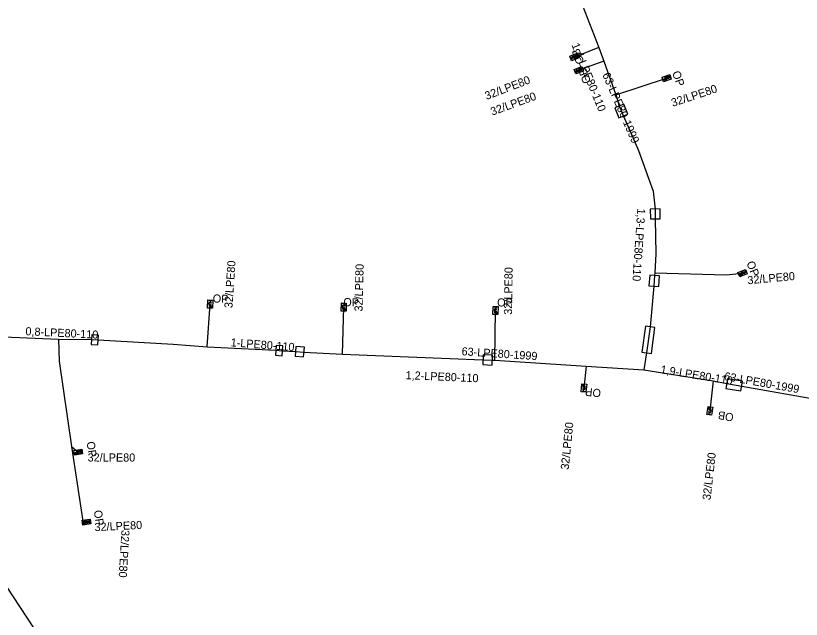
# Model space of a CAD drawing. Extents: x -762509 to -761250, y -1153000 to -1152256.
# Drawn here: x -761534.3 to -761437.4, y -1152558.6 to -1152484.2 of the extents above; entities that cross this region are included whole.
import ezdxf

# ---------------------------------------------------------------- set-up
doc = ezdxf.new("R2010")
doc.units = 0
for name, color, linetype in [('Vrstva 21', 7, 'Continuous'), ('Vrstva 29', 7, 'Continuous'), ('Vrstva 31', 7, 'Continuous'), ('Vrstva 32', 7, 'Continuous')]:
    doc.layers.add(name, color=color, linetype=linetype)

msp = doc.modelspace()

# ---------------------------------------------------------------- linework, layer by layer
at = {"layer": 'Vrstva 21'}
for points in [[(-761466.1, -1152478.45), (-761462.35, -1152488.13), (-761461.73, -1152489.79), (-761460.26, -1152493.95), (-761459.84, -1152495.33), (-761459.33, -1152496.58), (-761457.49, -1152500.82), (-761455.66, -1152505.82), (-761455.42, -1152508.04), (-761455.4, -1152509.24), (-761455.33, -1152513.56), (-761455.47, -1152515.91), (-761455.49, -1152516.25), (-761455.58, -1152517.56), (-761456.03, -1152522.58), (-761456.47, -1152525.78), (-761456.83, -1152527.87)], [(-761556.37, -1152527.31), (-761556.21, -1152527.12), (-761552.23, -1152522.56), (-761550.25, -1152522.69), (-761542.52, -1152523.31), (-761535.75, -1152523.8), (-761529, -1152524.1), (-761524.95, -1152524.15), (-761524.13, -1152524.19), (-761514.88, -1152524.71), (-761510.67, -1152525.03), (-761502.21, -1152525.46), (-761501.38, -1152525.53), (-761499.78, -1152525.61), (-761498.74, -1152525.69), (-761493.99, -1152525.96), (-761476.66, -1152526.63), (-761475.5, -1152526.68), (-761475.2, -1152526.7), (-761463.93, -1152527.44), (-761456.83, -1152527.87)], [(-761555.86, -1152527.89), (-761549.23, -1152535.25), (-761546.63, -1152538.48), (-761545.44, -1152539.91), (-761544.54, -1152541.17), (-761537.84, -1152551.04), (-761536.98, -1152552.22), (-761535.54, -1152554.43), (-761529.45, -1152563.76), (-761525.2, -1152570.86), (-761520.77, -1152578.65), (-761517.06, -1152586.65), (-761515.83, -1152589.42), (-761514.08, -1152593.75), (-761509.53, -1152605.92), (-761503.36, -1152620.97), (-761502.33, -1152623.3), (-761499.83, -1152629.35)], [(-761456.83, -1152527.87), (-761448.25, -1152529.25), (-761446.58, -1152529.57), (-761444.73, -1152529.87), (-761425.09, -1152533.35), (-761412.86, -1152535.83), (-761404.73, -1152537.14), (-761396.67, -1152538.6), (-761395, -1152538.89), (-761392.98, -1152539.26), (-761384.89, -1152540.72), (-761378.87, -1152541.76), (-761369.46, -1152544.68), (-761366.06, -1152546), (-761363.94, -1152546.96), (-761363.78, -1152547.02), (-761358.42, -1152549.62), (-761356.97, -1152550.5), (-761355.51, -1152551.26), (-761353.56, -1152552.55), (-761349.19, -1152555.34), (-761336.19, -1152563.79)]]:
    msp.add_lwpolyline(points, dxfattribs=at)
at = {"layer": 'Vrstva 29'}
for points in [[(-761460.4, -1152495.56), (-761459.89, -1152496.81), (-761458.77, -1152496.35), (-761459.28, -1152495.1)], [(-761456.02, -1152508.05), (-761456, -1152509.25), (-761454.8, -1152509.23), (-761454.82, -1152508.03)], [(-761456.09, -1152516.21), (-761456.18, -1152517.52), (-761454.98, -1152517.6), (-761454.89, -1152516.29)], [(-761455.88, -1152525.86), (-761455.44, -1152522.66), (-761456.62, -1152522.5), (-761457.06, -1152525.7)], [(-761524.98, -1152524.75), (-761524.16, -1152524.79), (-761524.1, -1152523.59), (-761524.92, -1152523.55)], [(-761502.26, -1152526.06), (-761501.43, -1152526.13), (-761501.33, -1152524.93), (-761502.16, -1152524.86)], [(-761499.83, -1152526.21), (-761498.79, -1152526.29), (-761498.69, -1152525.09), (-761499.73, -1152525.01)], [(-761476.69, -1152527.23), (-761475.53, -1152527.28), (-761475.47, -1152526.08), (-761476.63, -1152526.03)], [(-761446.68, -1152530.16), (-761444.83, -1152530.46), (-761444.63, -1152529.28), (-761446.48, -1152528.98)]]:
    msp.add_lwpolyline(points, close=True, dxfattribs=at)
at = {"layer": 'Vrstva 31'}
for points in [[(-761462.35, -1152488.13), (-761465.38, -1152489.29)], [(-761461.73, -1152489.79), (-761464.82, -1152490.92)], [(-761460.26, -1152493.95), (-761454, -1152491.89)], [(-761455.47, -1152515.91), (-761446.66, -1152516.14), (-761444.63, -1152515.95)], [(-761510.67, -1152525.03), (-761510.31, -1152519.76)], [(-761493.99, -1152525.96), (-761493.84, -1152520.13)], [(-761475.2, -1152526.7), (-761475.11, -1152520.56)], [(-761529, -1152524.1), (-761528.95, -1152526.81), (-761527.42, -1152537.35)], [(-761463.93, -1152527.44), (-761464.2, -1152530.12)], [(-761448.25, -1152529.25), (-761448.68, -1152532.94)], [(-761527.42, -1152537.35), (-761526.01, -1152546.55), (-761525.58, -1152546.66)], [(-761527.42, -1152537.35), (-761526.59, -1152538.03)]]:
    msp.add_lwpolyline(points, dxfattribs=at)
at = {"layer": 'Vrstva 32'}
for p, q in [((-761465.816, -1152489.269), (-761465.691, -1152489.596)), ((-761465.757, -1152489.423), (-761465.569, -1152489.352)), ((-761465.503, -1152489.524), (-761465.628, -1152489.198)), ((-761465.131, -1152489.382), (-761465.256, -1152489.055)), ((-761465.256, -1152490.893), (-761465.136, -1152491.222)), ((-761465.199, -1152491.048), (-761465.01, -1152490.979)), ((-761464.947, -1152491.153), (-761465.067, -1152490.824)), ((-761464.572, -1152491.015), (-761464.692, -1152490.687)), ((-761454.246, -1152491.791), (-761454.131, -1152492.122)), ((-761453.87, -1152491.659), (-761453.754, -1152491.99)), ((-761453.619, -1152491.767), (-761453.809, -1152491.834)), ((-761453.564, -1152491.923), (-761453.68, -1152491.593)), ((-761444.193, -1152515.962), (-761444.325, -1152515.637)), ((-761444.881, -1152515.862), (-761444.75, -1152516.187)), ((-761444.511, -1152515.713), (-761444.38, -1152516.037)), ((-761444.255, -1152515.809), (-761444.442, -1152515.884)), ((-761510.125, -1152519.364), (-761510.475, -1152519.356)), ((-761510.29, -1152519.36), (-761510.295, -1152519.561)), ((-761510.49, -1152519.956), (-761510.14, -1152519.964)), ((-761510.48, -1152519.557), (-761510.13, -1152519.565)), ((-761494.02, -1152520.325), (-761493.671, -1152520.335)), ((-761494.009, -1152519.926), (-761493.659, -1152519.936)), ((-761493.653, -1152519.735), (-761494.003, -1152519.725)), ((-761493.818, -1152519.73), (-761493.824, -1152519.931)), ((-761475.28, -1152520.357), (-761474.93, -1152520.366)), ((-761474.926, -1152520.165), (-761475.275, -1152520.156)), ((-761475.091, -1152520.161), (-761475.095, -1152520.362)), ((-761475.29, -1152520.756), (-761474.94, -1152520.764)), ((-761464.006, -1152529.938), (-761464.354, -1152529.903)), ((-761464.415, -1152530.5), (-761464.066, -1152530.535)), ((-761464.046, -1152530.335), (-761464.394, -1152530.3)), ((-761464.25, -1152530.517), (-761464.23, -1152530.317)), ((-761448.473, -1152532.773), (-761448.817, -1152532.712)), ((-761448.923, -1152533.303), (-761448.578, -1152533.364)), ((-761448.543, -1152533.166), (-761448.887, -1152533.105)), ((-761448.76, -1152533.332), (-761448.725, -1152533.134)), ((-761526.813, -1152537.886), (-761526.762, -1152538.232)), ((-761526.419, -1152537.828), (-761526.367, -1152538.174)), ((-761526.169, -1152538.145), (-761526.22, -1152537.798)), ((-761526.193, -1152537.981), (-761526.392, -1152538.011)), ((-761525.803, -1152546.516), (-761525.752, -1152546.863)), ((-761525.409, -1152546.458), (-761525.357, -1152546.804)), ((-761525.183, -1152546.611), (-761525.382, -1152546.641)), ((-761525.158, -1152546.775), (-761525.21, -1152546.428))]:
    msp.add_line(p, q, dxfattribs=at)
for points in [[(-761465.954, -1152489.188), (-761465.02, -1152488.831), (-761464.806, -1152489.391), (-761465.74, -1152489.749), (-761465.954, -1152489.188)], [(-761465.536, -1152489.162), (-761465.446, -1152489.397), (-761465.416, -1152489.437), (-761465.375, -1152489.457), (-761465.329, -1152489.458), (-761465.302, -1152489.448), (-761465.269, -1152489.417), (-761465.254, -1152489.375), (-761465.258, -1152489.325), (-761465.348, -1152489.09)], [(-761465.256, -1152489.055), (-761465.134, -1152489.008), (-761465.089, -1152489.009), (-761465.069, -1152489.019), (-761465.044, -1152489.045), (-761465.027, -1152489.091), (-761465.028, -1152489.127), (-761465.036, -1152489.147), (-761465.069, -1152489.178), (-761465.191, -1152489.225)], [(-761465.393, -1152490.81), (-761464.454, -1152490.466), (-761464.248, -1152491.03), (-761465.187, -1152491.373), (-761465.393, -1152490.81)], [(-761464.974, -1152490.79), (-761464.888, -1152491.026), (-761464.858, -1152491.067), (-761464.818, -1152491.087), (-761464.772, -1152491.089), (-761464.745, -1152491.079), (-761464.711, -1152491.048), (-761464.695, -1152491.007), (-761464.699, -1152490.957), (-761464.785, -1152490.721)], [(-761464.692, -1152490.687), (-761464.57, -1152490.642), (-761464.525, -1152490.644), (-761464.505, -1152490.654), (-761464.481, -1152490.68), (-761464.464, -1152490.727), (-761464.466, -1152490.762), (-761464.474, -1152490.783), (-761464.508, -1152490.813), (-761464.63, -1152490.858)], [(-761453.429, -1152492.008), (-761454.373, -1152492.339), (-761454.571, -1152491.772), (-761453.627, -1152491.442), (-761453.429, -1152492.008)], [(-761454.131, -1152492.122), (-761454.253, -1152492.164), (-761454.299, -1152492.162), (-761454.318, -1152492.152), (-761454.342, -1152492.126), (-761454.359, -1152492.078), (-761454.356, -1152492.043), (-761454.348, -1152492.023), (-761454.314, -1152491.993), (-761454.191, -1152491.95)], [(-761453.848, -1152492.022), (-761453.931, -1152491.785), (-761453.96, -1152491.744), (-761454, -1152491.723), (-761454.045, -1152491.721), (-761454.073, -1152491.73), (-761454.107, -1152491.76), (-761454.123, -1152491.801), (-761454.12, -1152491.852), (-761454.037, -1152492.089)], [(-761444.054, -1152516.04), (-761444.981, -1152516.415), (-761445.206, -1152515.859), (-761444.279, -1152515.484), (-761444.054, -1152516.04)], [(-761444.75, -1152516.187), (-761444.87, -1152516.236), (-761444.915, -1152516.236), (-761444.935, -1152516.226), (-761444.961, -1152516.201), (-761444.979, -1152516.155), (-761444.979, -1152516.119), (-761444.971, -1152516.098), (-761444.938, -1152516.067), (-761444.818, -1152516.018)], [(-761444.472, -1152516.074), (-761444.566, -1152515.842), (-761444.597, -1152515.801), (-761444.638, -1152515.782), (-761444.684, -1152515.782), (-761444.71, -1152515.793), (-761444.743, -1152515.825), (-761444.757, -1152515.866), (-761444.752, -1152515.917), (-761444.658, -1152516.15)], [(-761509.998, -1152519.268), (-761510.023, -1152520.267), (-761510.623, -1152520.252), (-761510.598, -1152519.253), (-761509.998, -1152519.268)], [(-761510.133, -1152519.664), (-761510.384, -1152519.658), (-761510.433, -1152519.671), (-761510.467, -1152519.701), (-761510.485, -1152519.743), (-761510.486, -1152519.772), (-761510.47, -1152519.814), (-761510.437, -1152519.844), (-761510.389, -1152519.859), (-761510.138, -1152519.865)], [(-761510.14, -1152519.964), (-761510.144, -1152520.094), (-761510.162, -1152520.136), (-761510.178, -1152520.15), (-761510.211, -1152520.164), (-761510.261, -1152520.162), (-761510.294, -1152520.147), (-761510.31, -1152520.132), (-761510.325, -1152520.09), (-761510.322, -1152519.96)], [(-761493.525, -1152519.639), (-761493.554, -1152520.638), (-761494.154, -1152520.621), (-761494.125, -1152519.622), (-761493.525, -1152519.639)], [(-761493.662, -1152520.035), (-761493.913, -1152520.028), (-761493.962, -1152520.04), (-761493.996, -1152520.07), (-761494.014, -1152520.112), (-761494.015, -1152520.141), (-761493.999, -1152520.183), (-761493.967, -1152520.213), (-761493.919, -1152520.229), (-761493.668, -1152520.236)], [(-761493.671, -1152520.335), (-761493.674, -1152520.465), (-761493.693, -1152520.506), (-761493.709, -1152520.521), (-761493.742, -1152520.534), (-761493.792, -1152520.533), (-761493.825, -1152520.518), (-761493.84, -1152520.502), (-761493.856, -1152520.46), (-761493.853, -1152520.33)], [(-761474.798, -1152520.068), (-761474.822, -1152521.067), (-761475.422, -1152521.053), (-761475.398, -1152520.053), (-761474.798, -1152520.068)], [(-761474.933, -1152520.464), (-761475.184, -1152520.459), (-761475.233, -1152520.471), (-761475.267, -1152520.502), (-761475.285, -1152520.543), (-761475.285, -1152520.572), (-761475.269, -1152520.615), (-761475.237, -1152520.644), (-761475.188, -1152520.66), (-761474.937, -1152520.665)], [(-761474.94, -1152520.764), (-761474.943, -1152520.894), (-761474.961, -1152520.936), (-761474.977, -1152520.951), (-761475.01, -1152520.964), (-761475.06, -1152520.963), (-761475.093, -1152520.948), (-761475.109, -1152520.932), (-761475.125, -1152520.89), (-761475.122, -1152520.76)], [(-761464.549, -1152530.587), (-761464.449, -1152529.592), (-761463.852, -1152529.652), (-761463.952, -1152530.647), (-761464.549, -1152530.587)], [(-761464.384, -1152530.202), (-761464.135, -1152530.227), (-761464.085, -1152530.218), (-761464.049, -1152530.19), (-761464.028, -1152530.15), (-761464.025, -1152530.121), (-761464.037, -1152530.078), (-761464.067, -1152530.046), (-761464.115, -1152530.027), (-761464.364, -1152530.002)], [(-761464.354, -1152529.903), (-761464.341, -1152529.774), (-761464.32, -1152529.734), (-761464.303, -1152529.721), (-761464.269, -1152529.71), (-761464.219, -1152529.715), (-761464.187, -1152529.732), (-761464.173, -1152529.749), (-761464.16, -1152529.792), (-761464.173, -1152529.922)], [(-761449.063, -1152533.379), (-761448.888, -1152532.395), (-761448.297, -1152532.5), (-761448.473, -1152533.485), (-761449.063, -1152533.379)], [(-761448.87, -1152533.007), (-761448.623, -1152533.051), (-761448.572, -1152533.046), (-761448.534, -1152533.021), (-761448.51, -1152532.983), (-761448.505, -1152532.955), (-761448.514, -1152532.91), (-761448.542, -1152532.876), (-761448.588, -1152532.853), (-761448.835, -1152532.809)], [(-761448.817, -1152532.712), (-761448.794, -1152532.584), (-761448.77, -1152532.546), (-761448.752, -1152532.534), (-761448.717, -1152532.526), (-761448.668, -1152532.534), (-761448.638, -1152532.554), (-761448.625, -1152532.572), (-761448.615, -1152532.616), (-761448.638, -1152532.744)], [(-761526.051, -1152538.254), (-761527.041, -1152538.4), (-761527.128, -1152537.807), (-761526.139, -1152537.66), (-761526.051, -1152538.254)], [(-761526.465, -1152538.189), (-761526.502, -1152537.94), (-761526.523, -1152537.894), (-761526.559, -1152537.866), (-761526.603, -1152537.855), (-761526.631, -1152537.859), (-761526.67, -1152537.882), (-761526.694, -1152537.919), (-761526.701, -1152537.97), (-761526.664, -1152538.218)], [(-761526.762, -1152538.232), (-761526.891, -1152538.252), (-761526.935, -1152538.241), (-761526.952, -1152538.227), (-761526.971, -1152538.197), (-761526.978, -1152538.147), (-761526.969, -1152538.113), (-761526.956, -1152538.094), (-761526.917, -1152538.072), (-761526.789, -1152538.052)], [(-761525.041, -1152546.884), (-761526.03, -1152547.03), (-761526.118, -1152546.437), (-761525.129, -1152546.29), (-761525.041, -1152546.884)], [(-761525.455, -1152546.819), (-761525.492, -1152546.57), (-761525.513, -1152546.524), (-761525.549, -1152546.496), (-761525.593, -1152546.485), (-761525.621, -1152546.489), (-761525.66, -1152546.512), (-761525.684, -1152546.549), (-761525.691, -1152546.6), (-761525.654, -1152546.848)], [(-761525.752, -1152546.863), (-761525.881, -1152546.882), (-761525.925, -1152546.871), (-761525.942, -1152546.857), (-761525.961, -1152546.827), (-761525.968, -1152546.777), (-761525.959, -1152546.743), (-761525.946, -1152546.725), (-761525.907, -1152546.702), (-761525.779, -1152546.682)]]:
    msp.add_lwpolyline(points, dxfattribs=at)

# ---------------------------------------------------------------- texts
at = {"layer": 'Vrstva 21'}
for rotation, p in [(293.45902, (-761461.96, -1152491.46)), (356.24329, (-761479.32, -1152526.07)), (349.90016, (-761446.96, -1152529.12))]:
    msp.add_text('63-LPE80-1999', height=1, rotation=rotation, dxfattribs=at).set_placement(p)
at = {"layer": 'Vrstva 29'}
for s, rotation, p in [('1,4-LPE80-110', 292.19546, (-761465.76, -1152487.79)), ('1,3-LPE80-110', 266.06982, (-761457.61, -1152507.94)), ('0,8-LPE80-110', 357.2073, (-761533.12, -1152523.6)), ('1-LPE80-110', 355.60129, (-761507.81, -1152524.97)), ('1,2-LPE80-110', 357.53188, (-761486.22, -1152529.02)), ('1,9-LPE80-110', 350.78897, (-761454.81, -1152528.29))]:
    msp.add_text(s, height=1, rotation=rotation, dxfattribs=at).set_placement(p)
at = {"layer": 'Vrstva 31'}
for rotation, p in [(20.94876, (-761476.21, -1152494.59)), (20.94876, (-761476.21, -1152494.59)), (18.215, (-761453.25, -1152495.44)), (18.215, (-761453.25, -1152495.44)), (20.08725, (-761475.51, -1152496.53)), (20.08725, (-761475.51, -1152496.53)), (86.09213, (-761507.57, -1152520.29)), (86.09213, (-761507.57, -1152520.29)), (88.52616, (-761491.52, -1152520.69)), (88.52616, (-761491.52, -1152520.69)), (89.16022, (-761473.08, -1152521.09)), (89.16022, (-761473.08, -1152521.09)), (5.34708, (-761443.99, -1152517.33)), (5.34708, (-761443.99, -1152517.33)), (84.24707, (-761466.09, -1152540.23)), (84.24707, (-761466.09, -1152540.23)), (359.85727, (-761525.43, -1152539.18)), (359.85727, (-761525.43, -1152539.18)), (83.35323, (-761448.6, -1152543.98)), (83.35323, (-761448.6, -1152543.98)), (2.76802, (-761524.55, -1152547.78)), (2.76802, (-761524.55, -1152547.78)), (266.60755, (-761521.25, -1152547.61)), (266.60755, (-761521.25, -1152547.61))]:
    msp.add_text('32/LPE80', height=1, rotation=rotation, dxfattribs=at).set_placement(p)
at = {"layer": 'Vrstva 32'}
for s, rotation, p in [('OB', 110.94876, (-761464.14, -1152489.94)), ('OB', 110.94876, (-761464.14, -1152489.94)), ('OB', 110.08725, (-761463.32, -1152492.35)), ('OB', 110.08725, (-761463.32, -1152492.35)), ('OP', 289.30594, (-761453.34, -1152491.2)), ('OP', 289.30594, (-761453.34, -1152491.2)), ('OP', 292.04207, (-761444.18, -1152514.69)), ('OP', 292.04207, (-761444.18, -1152514.69)), ('OP', 358.58336, (-761510, -1152519.57)), ('OP', 358.58336, (-761510, -1152519.57)), ('OP', 358.34589, (-761493.9, -1152520.01)), ('OP', 358.34589, (-761493.9, -1152520.01)), ('OP', 359.11653, (-761474.92, -1152520.05)), ('OP', 359.11653, (-761474.92, -1152520.05)), ('OP', 174.24708, (-761462.06, -1152530.28)), ('OP', 174.24708, (-761462.06, -1152530.28)), ('OB', 169.87782, (-761445.67, -1152533.29)), ('OB', 169.87782, (-761445.67, -1152533.29)), ('OP', 278.42697, (-761525.56, -1152536.79)), ('OP', 278.42697, (-761525.56, -1152536.79)), ('OP', 278.43156, (-761524.67, -1152545.25)), ('OP', 278.43156, (-761524.67, -1152545.25))]:
    msp.add_text(s, height=1, rotation=rotation, dxfattribs=at).set_placement(p)

doc.saveas('drawing.dxf')
